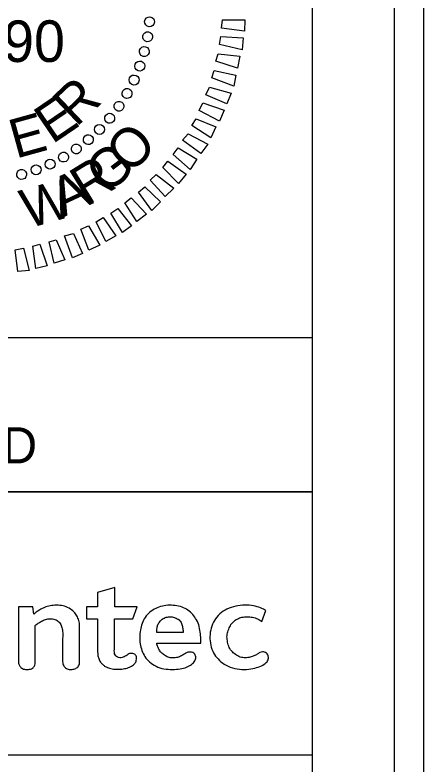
# Model space of a CAD drawing. Extents: x 2320980 to 2456309, y 595047 to 606177.
# Drawn here: x 2456033.07 to 2456045.51, y 597570.06 to 597592.89 of the extents above; entities that cross this region are included whole.
import ezdxf

# ---------------------------------------------------------------- set-up
doc = ezdxf.new("R2010")
doc.units = 0
for name, color, linetype in [('Default', 7, 'Continuous'), ('Scratch_Level_0', 7, 'Continuous'), ('Sheet Data Text CELL', 7, 'Continuous'), ('Sheet Plan CELL', 7, 'Continuous'), ('Sheet Plot Border Inside CELL', 7, 'Continuous'), ('Sheet Plot Border Outside CELL', 7, 'Continuous'), ('Sheet Sticker Exception Certification CELL', 7, 'Continuous')]:
    doc.layers.add(name, color=color, linetype=linetype)

msp = doc.modelspace()

# ---------------------------------------------------------------- linework, layer by layer
at = {"layer": 'Default'}
for p, q in [((2456037.167, 597592.673), (2456037.167, 597592.673)), ((2456037.167, 597592.673), (2456037.167, 597592.673)), ((2456037.102, 597592.218), (2456037.102, 597592.218)), ((2456037.102, 597592.218), (2456037.102, 597592.218)), ((2456037.015, 597591.774), (2456037.015, 597591.774)), ((2456037.015, 597591.774), (2456037.015, 597591.774)), ((2456036.876, 597591.329), (2456036.876, 597591.329)), ((2456036.876, 597591.329), (2456036.876, 597591.329)), ((2456036.695, 597590.905), (2456036.695, 597590.905)), ((2456036.695, 597590.905), (2456036.695, 597590.905)), ((2456036.492, 597590.49), (2456036.492, 597590.49)), ((2456036.492, 597590.49), (2456036.492, 597590.49)), ((2456036.236, 597590.106), (2456036.236, 597590.106)), ((2456036.236, 597590.106), (2456036.236, 597590.106)), ((2456035.958, 597589.721), (2456035.958, 597589.721)), ((2456035.958, 597589.721), (2456035.958, 597589.721)), ((2456035.649, 597589.399), (2456035.649, 597589.399)), ((2456035.649, 597589.399), (2456035.649, 597589.399)), ((2456035.297, 597589.077), (2456035.297, 597589.077)), ((2456035.297, 597589.077), (2456035.297, 597589.077)), ((2456034.943, 597588.807), (2456034.943, 597588.807)), ((2456034.943, 597588.807), (2456034.943, 597588.807)), ((2456034.548, 597588.557), (2456034.548, 597588.557)), ((2456034.548, 597588.557), (2456034.548, 597588.557)), ((2456034.141, 597588.339), (2456034.141, 597588.339)), ((2456034.141, 597588.339), (2456034.141, 597588.339)), ((2456033.283, 597588.028), (2456033.283, 597588.028)), ((2456033.283, 597588.028), (2456033.283, 597588.028)), ((2456033.713, 597588.162), (2456033.713, 597588.162)), ((2456033.713, 597588.162), (2456033.713, 597588.162))]:
    msp.add_line(p, q, dxfattribs=at)
for points in [[(2456039.377, 597592.735), (2456040.062, 597592.738), (2456040.048, 597592.39), (2456039.351, 597592.482)], [(2456039.334, 597592.229), (2456040.009, 597592.189), (2456039.974, 597591.831), (2456039.286, 597591.986)], [(2456039.25, 597591.701), (2456039.904, 597591.629), (2456039.837, 597591.269), (2456039.18, 597591.478)], [(2456039.123, 597591.193), (2456039.789, 597591.057), (2456039.721, 597590.719), (2456039.053, 597590.97)], [(2456038.985, 597590.685), (2456039.641, 597590.507), (2456039.51, 597590.178), (2456038.873, 597590.461)], [(2456038.782, 597590.217), (2456039.43, 597589.988), (2456039.288, 597589.658), (2456038.671, 597589.983)], [(2456038.581, 597589.729), (2456039.176, 597589.477), (2456039.024, 597589.147), (2456038.448, 597589.526)], [(2456038.337, 597589.271), (2456038.933, 597588.956), (2456038.718, 597588.668), (2456038.162, 597589.078)], [(2456038.029, 597588.844), (2456038.604, 597588.497), (2456038.4, 597588.188), (2456037.885, 597588.641)], [(2456037.721, 597588.438), (2456038.276, 597588.038), (2456038.039, 597587.759), (2456037.566, 597588.246)], [(2456037.36, 597588.031), (2456037.905, 597587.61), (2456037.636, 597587.362), (2456037.184, 597587.859)], [(2456037.02, 597587.656), (2456037.491, 597587.202), (2456037.233, 597586.933), (2456036.822, 597587.494)], [(2456036.604, 597587.322), (2456037.067, 597586.825), (2456036.776, 597586.598), (2456036.407, 597587.17)], [(2456036.2, 597586.998), (2456036.61, 597586.468), (2456036.34, 597586.263), (2456035.981, 597586.857)], [(2456035.752, 597586.726), (2456036.141, 597586.165), (2456035.829, 597585.99), (2456035.544, 597586.585)], [(2456035.304, 597586.465), (2456035.652, 597585.881), (2456035.317, 597585.728), (2456035.074, 597586.366)], [(2456034.845, 597586.235), (2456035.119, 597585.629), (2456034.817, 597585.497), (2456034.572, 597586.167)], [(2456034.322, 597586.046), (2456034.586, 597585.43), (2456034.261, 597585.329), (2456034.112, 597585.979)], [(2456033.325, 597585.785), (2456033.507, 597585.104), (2456033.16, 597585.076), (2456033.074, 597585.738)], [(2456033.829, 597585.91), (2456034.052, 597585.251), (2456033.706, 597585.171), (2456033.609, 597585.854)]]:
    msp.add_lwpolyline(points, close=True, dxfattribs=at)
for centre, major_axis in [((2456037.163, 597592.68), (0.151, -0.013)), ((2456037.103, 597592.223), (0.149, -0.026)), ((2456037.004, 597591.773), (0.147, -0.039)), ((2456036.866, 597591.333), (0.143, -0.052)), ((2456036.691, 597590.907), (0.138, -0.064)), ((2456036.478, 597590.498), (0.131, -0.076)), ((2456036.231, 597590.109), (0.124, -0.087)), ((2456035.951, 597589.743), (0.116, -0.097)), ((2456035.64, 597589.403), (0.107, -0.107)), ((2456035.301, 597589.091), (0.098, -0.116)), ((2456034.936, 597588.81), (0.087, -0.124)), ((2456034.548, 597588.562), (0.076, -0.131)), ((2456034.139, 597588.349), (0.064, -0.137)), ((2456033.714, 597588.172), (0.052, -0.142)), ((2456033.274, 597588.033), (0.039, -0.146))]:
    msp.add_ellipse(centre, major_axis=major_axis, ratio=0.999708, dxfattribs=at)
at = {"layer": 'Scratch_Level_0'}
msp.add_lwpolyline([(2456019.333, 597578.364), (2456042.107, 597578.366), (2456042.108, 597570.357), (2456019.334, 597570.354)], close=True, dxfattribs=at)
at = {"layer": 'Sheet Data Text CELL'}
for p, q in [((2456036.102, 597575.458), (2456035.576, 597575.311)), ((2456036.102, 597574.873), (2456036.102, 597575.458)), ((2456035.576, 597575.311), (2456035.576, 597574.873)), ((2456033.616, 597574.872), (2456033.173, 597574.872)), ((2456033.173, 597574.872), (2456033.173, 597573.193)), ((2456033.645, 597574.649), (2456033.616, 597574.872)), ((2456035.576, 597574.873), (2456035.241, 597574.873)), ((2456035.241, 597574.873), (2456035.241, 597574.507)), ((2456036.783, 597574.873), (2456036.102, 597574.873)), ((2456036.655, 597574.507), (2456036.783, 597574.873)), ((2456040.58, 597574.419), (2456040.696, 597574.763)), ((2456035.241, 597574.507), (2456035.58, 597574.507)), ((2456036.092, 597573.582), (2456036.099, 597574.507)), ((2456036.099, 597574.507), (2456036.655, 597574.507)), ((2456033.689, 597573.194), (2456033.689, 597574.301)), ((2456038.184, 597574.091), (2456037.381, 597574.091)), ((2456037.381, 597573.769), (2456038.717, 597573.769))]:
    msp.add_line(p, q, dxfattribs=at)
for points in [[(2456033.689, 597574.301), (2456033.697, 597574.309), (2456033.733, 597574.342), (2456033.819, 597574.395), (2456033.931, 597574.468), (2456034.073, 597574.512), (2456034.217, 597574.51), (2456034.356, 597574.466), (2456034.451, 597574.367), (2456034.503, 597574.248), (2456034.53, 597574.088), (2456034.513, 597573.849), (2456034.525, 597573.546), (2456034.509, 597573.294), (2456034.52, 597573.119), (2456034.58, 597573.026), (2456034.685, 597572.959), (2456034.807, 597572.961), (2456034.923, 597572.99), (2456035.018, 597573.061), (2456035.045, 597573.2), (2456035.025, 597573.444), (2456035.038, 597573.744), (2456035.031, 597574.074), (2456035.043, 597574.283), (2456035.015, 597574.466), (2456034.958, 597574.594), (2456034.867, 597574.725), (2456034.721, 597574.827), (2456034.537, 597574.914), (2456034.327, 597574.92), (2456034.138, 597574.909), (2456033.968, 597574.853), (2456033.817, 597574.782), (2456033.716, 597574.703), (2456033.663, 597574.662), (2456033.645, 597574.649)], [(2456038.717, 597573.769), (2456038.719, 597573.819), (2456038.723, 597573.948), (2456038.7, 597574.153), (2456038.648, 597574.384), (2456038.537, 597574.562), (2456038.412, 597574.717), (2456038.253, 597574.826), (2456038.051, 597574.906), (2456037.825, 597574.92), (2456037.603, 597574.916), (2456037.392, 597574.849), (2456037.211, 597574.746), (2456037.054, 597574.597), (2456036.947, 597574.415), (2456036.887, 597574.216), (2456036.864, 597574.013), (2456036.861, 597573.795), (2456036.91, 597573.593), (2456036.99, 597573.395), (2456037.112, 597573.226), (2456037.298, 597573.092), (2456037.529, 597572.978), (2456037.798, 597572.964), (2456038.043, 597572.967), (2456038.251, 597573.011), (2456038.415, 597573.091), (2456038.534, 597573.194), (2456038.578, 597573.307), (2456038.558, 597573.398), (2456038.513, 597573.471), (2456038.441, 597573.491), (2456038.37, 597573.5), (2456038.288, 597573.474), (2456038.191, 597573.414), (2456038.08, 597573.346), (2456037.944, 597573.316), (2456037.818, 597573.312), (2456037.694, 597573.344), (2456037.591, 597573.415), (2456037.489, 597573.499), (2456037.429, 597573.61), (2456037.392, 597573.701), (2456037.384, 597573.751), (2456037.381, 597573.769)], [(2456040.696, 597574.763), (2456040.652, 597574.787), (2456040.542, 597574.849), (2456040.329, 597574.904), (2456040.063, 597574.932), (2456039.78, 597574.9), (2456039.509, 597574.811), (2456039.286, 597574.662), (2456039.125, 597574.459), (2456039.025, 597574.226), (2456038.99, 597573.963), (2456039.011, 597573.699), (2456039.101, 597573.461), (2456039.235, 597573.279), (2456039.421, 597573.12), (2456039.676, 597573.002), (2456039.975, 597572.954), (2456040.249, 597572.972), (2456040.476, 597573.032), (2456040.655, 597573.115), (2456040.772, 597573.227), (2456040.778, 597573.335), (2456040.768, 597573.415), (2456040.714, 597573.463), (2456040.659, 597573.496), (2456040.598, 597573.5), (2456040.516, 597573.487), (2456040.443, 597573.423), (2456040.336, 597573.379), (2456040.23, 597573.328), (2456040.077, 597573.317), (2456039.918, 597573.331), (2456039.765, 597573.414), (2456039.65, 597573.529), (2456039.558, 597573.668), (2456039.53, 597573.832), (2456039.506, 597573.994), (2456039.552, 597574.154), (2456039.614, 597574.301), (2456039.705, 597574.418), (2456039.828, 597574.505), (2456039.968, 597574.559), (2456040.132, 597574.573), (2456040.296, 597574.557), (2456040.453, 597574.507), (2456040.539, 597574.447), (2456040.58, 597574.419)], [(2456037.381, 597574.091), (2456037.381, 597574.107), (2456037.381, 597574.149), (2456037.386, 597574.227), (2456037.412, 597574.327), (2456037.475, 597574.433), (2456037.572, 597574.519), (2456037.705, 597574.566), (2456037.847, 597574.569), (2456037.98, 597574.529), (2456038.093, 597574.456), (2456038.149, 597574.333), (2456038.177, 597574.21), (2456038.182, 597574.127), (2456038.184, 597574.091)], [(2456035.58, 597574.507), (2456035.578, 597574.18), (2456035.577, 597573.835), (2456035.58, 597573.45), (2456035.598, 597573.358), (2456035.634, 597573.232), (2456035.705, 597573.147), (2456035.778, 597573.08), (2456035.854, 597573.029), (2456035.977, 597572.986), (2456036.145, 597572.967), (2456036.319, 597572.975), (2456036.492, 597572.999), (2456036.624, 597573.066), (2456036.721, 597573.145), (2456036.767, 597573.235), (2456036.772, 597573.314), (2456036.757, 597573.38), (2456036.722, 597573.419), (2456036.681, 597573.444), (2456036.631, 597573.453), (2456036.579, 597573.454), (2456036.527, 597573.441), (2456036.48, 597573.403), (2456036.427, 597573.363), (2456036.361, 597573.335), (2456036.292, 597573.312), (2456036.221, 597573.32), (2456036.159, 597573.354), (2456036.11, 597573.402), (2456036.09, 597573.485), (2456036.091, 597573.544), (2456036.092, 597573.582)], [(2456033.173, 597573.193), (2456033.178, 597573.171), (2456033.189, 597573.122), (2456033.226, 597573.037), (2456033.32, 597572.965), (2456033.451, 597572.964), (2456033.583, 597572.973), (2456033.661, 597573.06), (2456033.689, 597573.135), (2456033.689, 597573.176), (2456033.689, 597573.194)]]:
    msp.add_open_spline(points, degree=3, dxfattribs=at)
at = {"layer": 'Sheet Plan CELL'}
for points in [[(2455742.104, 597403.076), (2455742.099, 597613.071), (2456002.097, 597613.079), (2456002.099, 597583.066), (2456042.107, 597583.064), (2456042.107, 597403.076)], [(2456042.112, 597613.076), (2455742.104, 597613.076), (2455742.104, 597403.076), (2456042.107, 597403.076)], [(2456022.107, 597605.564), (2456042.104, 597605.566), (2456042.107, 597583.064), (2456022.107, 597583.061)]]:
    msp.add_lwpolyline(points, close=True, dxfattribs=at)
at = {"layer": 'Sheet Plot Border Inside CELL'}
msp.add_lwpolyline([(2455711.407, 597402.574), (2456044.604, 597402.576), (2456044.607, 597613.574), (2455711.407, 597613.574)], close=True, dxfattribs=at)
at = {"layer": 'Sheet Plot Border Outside CELL'}
msp.add_lwpolyline([(2455708.807, 597398.574), (2456045.507, 597398.574), (2456045.507, 597617.574), (2455708.807, 597617.574)], close=True, dxfattribs=at)
at = {"layer": 'Sheet Sticker Exception Certification CELL'}
for p, q in [((2456002.099, 597583.066), (2456042.107, 597583.066)), ((2456002.099, 597583.066), (2456042.107, 597583.066)), ((2456042.107, 597583.064), (2456042.107, 597578.364)), ((2456042.107, 597583.064), (2456042.107, 597578.364)), ((2456042.107, 597578.366), (2456002.099, 597578.366)), ((2456042.107, 597578.366), (2456002.099, 597578.366))]:
    msp.add_line(p, q, dxfattribs=at)

# ---------------------------------------------------------------- texts
at = {"layer": 'Default'}
for s, height, rotation, p in [('044590', 1.2638, 0.081, (2456028.951, 597591.451)), ('R', 1.188, 43.5624, (2456034.931, 597589.449)), ('E', 1.188, 34.205, (2456034.203, 597588.94)), ('E', 1.188, 15.4927, (2456033.095, 597588.509)), ('O', 1.188, 45.0203, (2456036.566, 597588.007)), ('G', 1.188, 37.0537, (2456035.811, 597587.41)), ('R', 1.188, 31.4977, (2456035.238, 597587.058)), ('A', 1.188, 24.9316, (2456034.522, 597586.717)), ('W', 1.188, 15.6219, (2456033.45, 597586.377))]:
    msp.add_text(s, height=height, rotation=rotation, dxfattribs=at).set_placement(p)
at = {"layer": 'Sheet Sticker Exception Certification CELL'}
msp.add_text('UNLESS ALL SIGNATURES COMPLETED', height=1.1, dxfattribs=at).set_placement((2456005.299, 597579.237))
msp.add_text('UNLESS ALL SIGNATURES COMPLETED', height=1.1, dxfattribs=at).set_placement((2456005.299, 597579.237))

doc.saveas('drawing.dxf')
